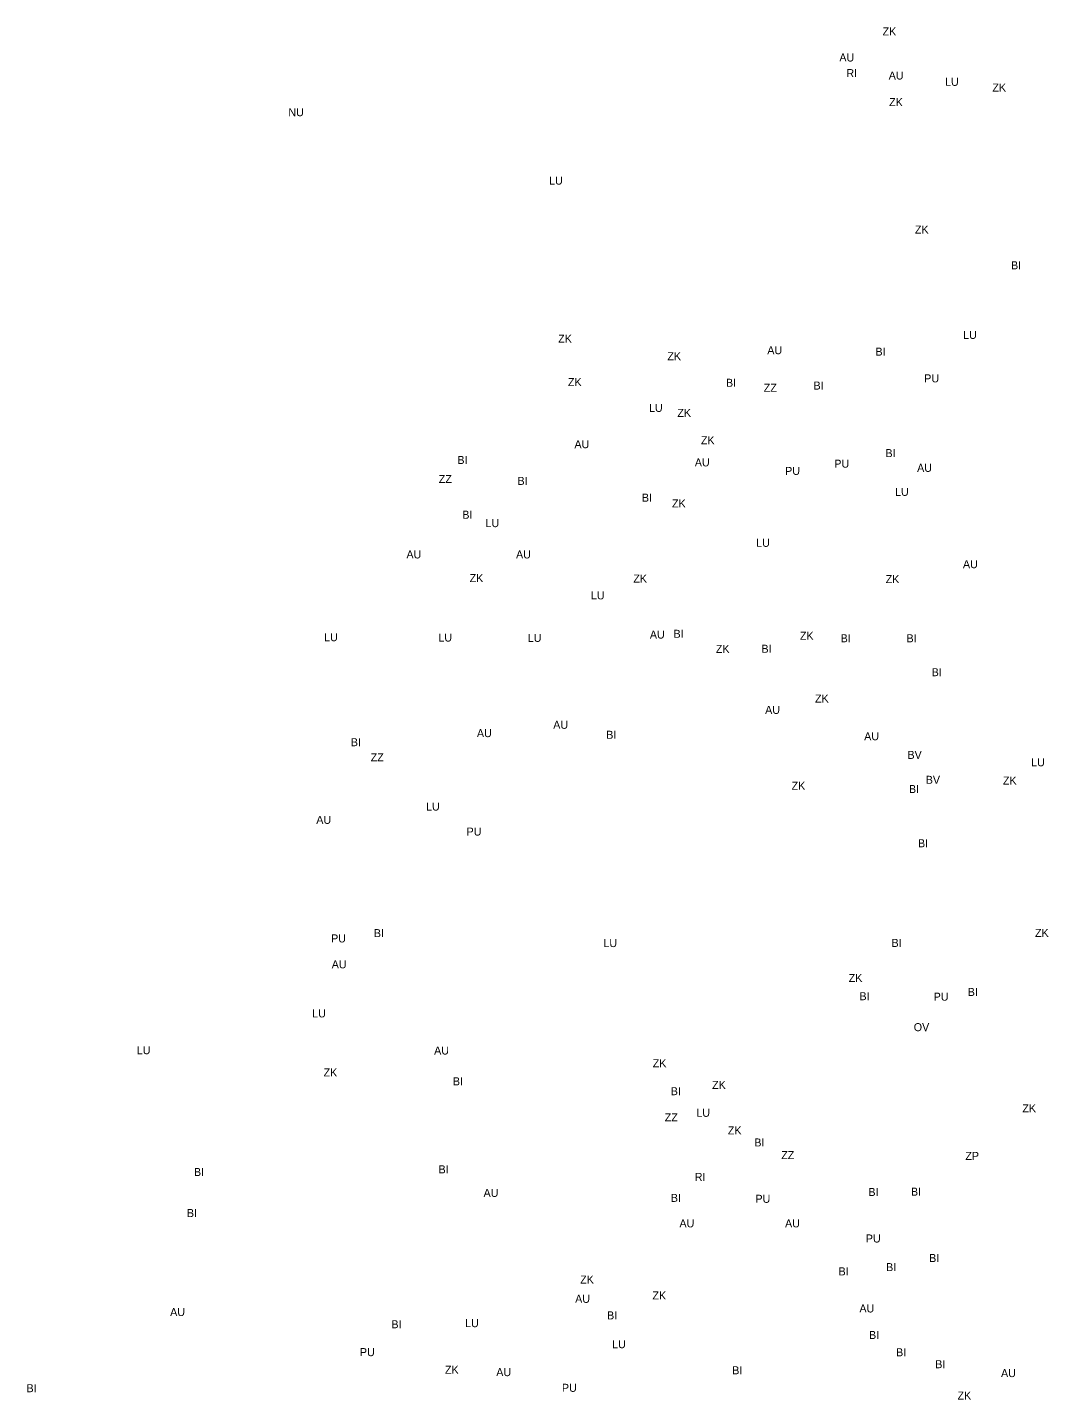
# Model space of a CAD drawing. Extents: x -439151 to -433911, y -1129946 to -1121460.
# Drawn here: x -439073 to -437796, y -1123589 to -1121874 of the extents above; entities that cross this region are included whole.
import ezdxf

# ---------------------------------------------------------------- set-up
doc = ezdxf.new("R2010")
doc.units = 0
doc.layers.add('POPIS PRESTAVBA', color=7, linetype='Continuous')
doc.layers.add('ZASTAVITELNA PLOCHA', color=7, linetype='Continuous')

msp = doc.modelspace()

# ---------------------------------------------------------------- texts
at = {"layer": 'POPIS PRESTAVBA'}
for s, p in [('ZK', (-438004, -1121884.3)), ('AU', (-438058, -1121916.9)), ('RI', (-438049.2, -1121936.4)), ('AU', (-437996.3, -1121939.4)), ('LU', (-437925.9, -1121947.3)), ('ZK', (-437866.7, -1121954.5)), ('ZK', (-437995.8, -1121972.7)), ('NU', (-438746.8, -1121985.3)), ('LU', (-438420.9, -1122070.8)), ('ZK', (-437963.5, -1122131.9)), ('BI', (-437843.4, -1122176.6)), ('ZK', (-438409.5, -1122268.3)), ('LU', (-437903.3, -1122263.6)), ('AU', (-438148.1, -1122282.7)), ('BI', (-438012.9, -1122284.5)), ('ZK', (-438273, -1122290.2)), ('ZK', (-438397.3, -1122322.5)), ('BI', (-438199.7, -1122323.4)), ('PU', (-437951.9, -1122317.9)), ('ZZ', (-438152.5, -1122329.6)), ('BI', (-438090.3, -1122326.9)), ('LU', (-438296, -1122354.8)), ('ZK', (-438260.5, -1122361)), ('AU', (-438389.2, -1122400.2)), ('ZK', (-438231.1, -1122395.2)), ('BI', (-438535.5, -1122419.9)), ('AU', (-438238.7, -1122422.9)), ('PU', (-438064.3, -1122424.5)), ('BI', (-438000.4, -1122411.3)), ('ZZ', (-438558.8, -1122443.7)), ('PU', (-438125.8, -1122433.6)), ('AU', (-437960.8, -1122429.7)), ('BI', (-438460.3, -1122446)), ('LU', (-437988.4, -1122459.7)), ('BI', (-438304.9, -1122467)), ('ZK', (-438267.2, -1122474.2)), ('BI', (-438529.3, -1122488.3)), ('LU', (-438500.3, -1122498.8)), ('LU', (-438162, -1122523.4)), ('AU', (-438599.2, -1122537.9)), ('AU', (-438462.2, -1122537.9)), ('AU', (-437903.5, -1122550.1)), ('ZK', (-438520.2, -1122567.5)), ('ZK', (-438315.6, -1122568.1)), ('ZK', (-438000.1, -1122568.8)), ('LU', (-438368.6, -1122589.1)), ('LU', (-438702.1, -1122641.4)), ('LU', (-438559.3, -1122641.8)), ('LU', (-438447.5, -1122642.2)), ('AU', (-438294.9, -1122638.1)), ('BI', (-438265.3, -1122637.1)), ('ZK', (-438107.3, -1122639.6)), ('BI', (-438056.4, -1122642.7)), ('BI', (-437974, -1122642.7)), ('ZK', (-438212.4, -1122656)), ('BI', (-438155.4, -1122655.8)), ('BI', (-437942.6, -1122685.1)), ('ZK', (-438088.4, -1122718)), ('AU', (-438150.8, -1122732.2)), ('AU', (-438415.7, -1122750.8)), ('AU', (-438511.1, -1122761.2)), ('BI', (-438349.4, -1122763.3)), ('AU', (-438027, -1122765.2)), ('BI', (-438668.7, -1122772.6)), ('ZZ', (-438643.9, -1122791.5)), ('LU', (-437818.3, -1122797.7)), ('ZK', (-437853.5, -1122820.5)), ('ZK', (-438117.7, -1122827)), ('BI', (-437971, -1122831.1)), ('LU', (-438574.7, -1122853.1)), ('AU', (-438711.9, -1122869.6)), ('PU', (-438524, -1122884.3)), ('BI', (-437959.7, -1122898.9)), ('PU', (-438693.4, -1123017.8)), ('BI', (-438639.9, -1123011.2)), ('LU', (-438353, -1123023.6)), ('BI', (-437992.7, -1123023.4)), ('ZK', (-437813.4, -1123010.9)), ('AU', (-438692.6, -1123050.2)), ('ZK', (-438046.3, -1123067.2)), ('BI', (-438032.9, -1123090)), ('PU', (-437940.1, -1123090.6)), ('BI', (-437897.5, -1123084.7)), ('LU', (-438717, -1123111.5)), ('OV', (-437965, -1123128.7)), ('LU', (-438936.3, -1123157.5)), ('AU', (-438564.6, -1123157.9)), ('ZK', (-438291.3, -1123173.8)), ('ZK', (-438702.8, -1123185.3)), ('BI', (-438541.2, -1123196.4)), ('BI', (-438268.8, -1123208.7)), ('ZK', (-438217.1, -1123200.9)), ('ZK', (-437829.2, -1123230.1)), ('ZZ', (-438276.3, -1123241.4)), ('LU', (-438236.8, -1123235.7)), ('ZK', (-438197.4, -1123257.7)), ('BI', (-438164.3, -1123272.8)), ('ZZ', (-438130.7, -1123288.6)), ('BI', (-438864.8, -1123309.7)), ('BI', (-438559.1, -1123306.4)), ('RI', (-438238.8, -1123315.8)), ('AU', (-438502.8, -1123335.8)), ('BI', (-438021.7, -1123334.7)), ('BI', (-438268.7, -1123342)), ('PU', (-438162.9, -1123343.2)), ('BI', (-438873.6, -1123361)), ('AU', (-438257.9, -1123373.9)), ('AU', (-438125.9, -1123373.9)), ('PU', (-438024.9, -1123392.8)), ('BI', (-437945.8, -1123417.2)), ('BI', (-438059, -1123433.9)), ('ZK', (-438382, -1123444.1)), ('AU', (-438388.3, -1123468.2)), ('ZK', (-438291.7, -1123464)), ('AU', (-438894.6, -1123484.7)), ('BI', (-438348.4, -1123488.9)), ('AU', (-438032.9, -1123480.2)), ('BI', (-438618, -1123500)), ('LU', (-438525.9, -1123498.6)), ('PU', (-438657.4, -1123534.8)), ('LU', (-438342.1, -1123524.9)), ('ZK', (-438551, -1123556.8)), ('BI', (-438191.9, -1123557.5)), ('BI', (-437938.1, -1123549.9)), ('AU', (-438486.9, -1123559.8)), ('AU', (-437855.9, -1123561)), ('BI', (-439074.1, -1123579.9)), ('PU', (-438404.8, -1123579.4)), ('ZK', (-437910.3, -1123589.1))]:
    msp.add_text(s, height=10, dxfattribs=at).set_placement(p)
at = {"layer": 'ZASTAVITELNA PLOCHA'}
for s, p in [('BV', (-437972.9, -1122788.4)), ('BV', (-437950, -1122819.6)), ('ZP', (-437900.5, -1123289.6)), ('BI', (-437968.5, -1123334.3)), ('BI', (-437999.6, -1123428.6)), ('BI', (-438020.9, -1123513.4)), ('BI', (-437987.1, -1123535))]:
    msp.add_text(s, height=10, dxfattribs=at).set_placement(p)

doc.saveas('drawing.dxf')
